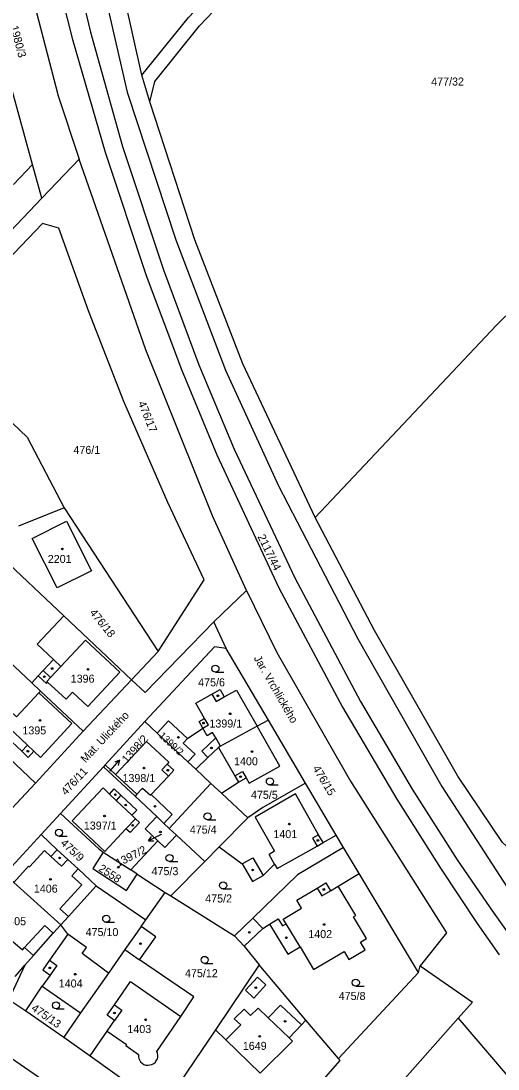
# Model space of a CAD drawing. Extents: x -679220 to -673243, y -1075091 to -1066557.
# Drawn here: x -675699.3 to -675598.1, y -1072325.9 to -1072103.3 of the extents above; entities that cross this region are included whole.
import ezdxf

# ---------------------------------------------------------------- set-up
doc = ezdxf.new("R2010")
doc.units = 0
for name, color, linetype in [('Hranice parcel', 7, 'Continuous'), ('Parcelní čísla', 7, 'Continuous'), ('Pop  PČ popisy', 7, 'Continuous'), ('Poz předměty', 7, 'Continuous'), ('Vnitřní kresba', 7, 'Continuous'), ('Značky budov', 7, 'Continuous'), ('Značky kultur', 7, 'Continuous')]:
    doc.layers.add(name, color=color, linetype=linetype)

msp = doc.modelspace()

# ---------------------------------------------------------------- linework, layer by layer
at = {"layer": 'Hranice parcel'}
for p, q in [((-675673.66, -1072114.8), (-675686.88, -1072055.23)), ((-675671.95, -1072120.45), (-675673.66, -1072114.8)), ((-675696.86, -1072133.78), (-675701.37, -1072117.47)), ((-675700.9, -1072138.01), (-675696.86, -1072133.78)), ((-675694.91, -1072140.93), (-675696.86, -1072133.78)), ((-675687, -1072132.64), (-675694.91, -1072140.93)), ((-675690.19, -1072206.73), (-675699.85, -1072210.59)), ((-675690.19, -1072206.73), (-675670.21, -1072237.22)), ((-675704.87, -1072215.84), (-675690.25, -1072229.64)), ((-675658.41, -1072230.92), (-675651.43, -1072224.24)), ((-675697.03, -1072243.89), (-675715.28, -1072226.72)), ((-675690.25, -1072229.64), (-675675.87, -1072243.22)), ((-675655.8, -1072236.62), (-675658.41, -1072230.92)), ((-675646.8, -1072251.8), (-675655.8, -1072236.62)), ((-675670.21, -1072237.22), (-675675.87, -1072243.22)), ((-675686.1, -1072254.17), (-675675.87, -1072243.22)), ((-675697.03, -1072243.89), (-675695.17, -1072245.64)), ((-675686.1, -1072254.17), (-675695.17, -1072245.64)), ((-675673.03, -1072252.09), (-675681.45, -1072261.29)), ((-675670.41, -1072254.55), (-675673.03, -1072252.09)), ((-675646.8, -1072251.8), (-675649.22, -1072253.12)), ((-675638.91, -1072265.18), (-675646.8, -1072251.8)), ((-675696.22, -1072265.18), (-675686.1, -1072254.17)), ((-675663.89, -1072260.67), (-675670.41, -1072254.55)), ((-675681.45, -1072261.29), (-675681.83, -1072261.71)), ((-675662.19, -1072262.26), (-675663.89, -1072260.67)), ((-675681.83, -1072261.71), (-675690.93, -1072271.66)), ((-675675.12, -1072267.99), (-675681.83, -1072261.71)), ((-675659.01, -1072265.24), (-675662.19, -1072262.26)), ((-675705.9, -1072275.51), (-675696.22, -1072265.18)), ((-675667.86, -1072274.8), (-675659.01, -1072265.24)), ((-675659.01, -1072265.24), (-675656.74, -1072267.36)), ((-675632.4, -1072276.24), (-675638.91, -1072265.18)), ((-675670.52, -1072272.31), (-675675.12, -1072267.99)), ((-675651.17, -1072272.59), (-675656.74, -1072267.36)), ((-675690.93, -1072271.66), (-675695.05, -1072276.14)), ((-675651.17, -1072272.59), (-675657.25, -1072278.74)), ((-675695.05, -1072276.14), (-675702.81, -1072284.58)), ((-675666.31, -1072276.26), (-675667.86, -1072274.8)), ((-675660.33, -1072281.85), (-675666.31, -1072276.26)), ((-675630.88, -1072278.84), (-675632.4, -1072276.24)), ((-675675.99, -1072283.61), (-675670.3, -1072277.43)), ((-675657.25, -1072278.74), (-675660.33, -1072281.85)), ((-675627.53, -1072284.42), (-675630.88, -1072278.84)), ((-675681.87, -1072279.86), (-675675.99, -1072283.61)), ((-675674.69, -1072284.54), (-675675.99, -1072283.61)), ((-675660.33, -1072281.85), (-675667.54, -1072289.14)), ((-675674.69, -1072284.54), (-675668.69, -1072288.42)), ((-675614.96, -1072305.4), (-675627.53, -1072284.42)), ((-675683.37, -1072287.03), (-675672.8, -1072294.25)), ((-675672.8, -1072294.25), (-675668.69, -1072288.42)), ((-675668.69, -1072288.42), (-675667.54, -1072289.14)), ((-675667.54, -1072289.14), (-675654.03, -1072297.62)), ((-675673.81, -1072295.67), (-675672.8, -1072294.25)), ((-675654.03, -1072297.62), (-675651.92, -1072299.85)), ((-675651.92, -1072299.85), (-675648.74, -1072303.81)), ((-675698.51, -1072303.87), (-675696.67, -1072301.8)), ((-675698.51, -1072303.87), (-675701.9, -1072311.14)), ((-675700.58, -1072306.26), (-675698.51, -1072303.87)), ((-675680.72, -1072305.54), (-675686.66, -1072313.99)), ((-675648.74, -1072303.81), (-675658.05, -1072317.58)), ((-675638.83, -1072315.52), (-675648.74, -1072303.81)), ((-675631.9, -1072323.72), (-675614.96, -1072305.4)), ((-675614.96, -1072305.4), (-675614.58, -1072304.01)), ((-675701.9, -1072311.14), (-675698.3, -1072313.6)), ((-675698.3, -1072313.6), (-675690.25, -1072319.15)), ((-675686.66, -1072313.99), (-675690.25, -1072319.15)), ((-675631.9, -1072323.72), (-675638.83, -1072315.52)), ((-675635.81, -1072348.19), (-675606.52, -1072315.16)), ((-675690.25, -1072319.15), (-675684.63, -1072323.15)), ((-675658.05, -1072317.58), (-675669.24, -1072334.12)), ((-675684.63, -1072323.15), (-675669.24, -1072334.12))]:
    msp.add_line(p, q, dxfattribs=at)
for points in [[(-675734.17, -1071838.14), (-675727.92, -1071869.06), (-675703.55, -1071993.04), (-675690.45, -1072058.85), (-675676.8, -1072118.37), (-675666.48, -1072149.75), (-675655.92, -1072177.48), (-675644.67, -1072202.06), (-675627.82, -1072234.57), (-675609.97, -1072265.91), (-675595.28, -1072288.62)], [(-675673.66, -1072114.8), (-675663.74, -1072102.5), (-675644.16, -1072081.76), (-675598.34, -1072038.2)], [(-675671.95, -1072120.45), (-675670.91, -1072116.13), (-675661.41, -1072104.3), (-675642.11, -1072083.95), (-675596.14, -1072040.03)], [(-675702.81, -1072072.97), (-675698.86, -1072090.46), (-675691.46, -1072119.14), (-675687, -1072132.64)], [(-675527.13, -1072097.75), (-675598.36, -1072167.91), (-675636.9, -1072208.76)], [(-675636.9, -1072208.76), (-675652.22, -1072176.08), (-675662.43, -1072149.75), (-675671.95, -1072120.45)], [(-675651.43, -1072224.24), (-675658.67, -1072208.41), (-675672.85, -1072173.15), (-675687, -1072132.64)], [(-675694.91, -1072140.93), (-675721.81, -1072169.15), (-675719.13, -1072171.69)], [(-675670.21, -1072237.22), (-675660.45, -1072222.03), (-675668.15, -1072205.56), (-675677.49, -1072184.08), (-675684.97, -1072164.88), (-675691.29, -1072147.32), (-675694.77, -1072146.33), (-675719.13, -1072171.69)], [(-675705.88, -1072184.22), (-675697.99, -1072191.67), (-675690.19, -1072206.73)], [(-675689.66, -1072209.53), (-675684.35, -1072220.08), (-675691.63, -1072223.67), (-675696.93, -1072213.21), (-675689.66, -1072209.53)], [(-675588.59, -1072283.25), (-675590.86, -1072283.57), (-675597.09, -1072277.84), (-675606.59, -1072263.7), (-675624.31, -1072232.74), (-675636.9, -1072208.76)], [(-675651.43, -1072224.24), (-675645.02, -1072237.47), (-675629.39, -1072264.76), (-675609.01, -1072296.97), (-675614.58, -1072304.01)], [(-675690.25, -1072229.64), (-675695.91, -1072235.64), (-675692.45, -1072238.94), (-675694.63, -1072241.26), (-675695.69, -1072242.4), (-675697.03, -1072243.89)], [(-675675.87, -1072243.22), (-675673, -1072245.92), (-675658.41, -1072230.92)], [(-675655.8, -1072236.62), (-675658.25, -1072236.27), (-675673.03, -1072252.09)], [(-675675.24, -1072344.8), (-675677.06, -1072343.56), (-675675.65, -1072341.45), (-675809.62, -1072248.86), (-675810.47, -1072252.39), (-675814.41, -1072249.48), (-675828.02, -1072240.66), (-675831.19, -1072238.38)], [(-675695.17, -1072245.64), (-675695.53, -1072246.03), (-675700.26, -1072251.11), (-675700.48, -1072250.91), (-675706.57, -1072245.42), (-675711.73, -1072250.64)], [(-675663.99, -1072255.71), (-675660.73, -1072253.52), (-675661.52, -1072252.12), (-675660.34, -1072251.45), (-675662.19, -1072248.19), (-675658.8, -1072246.3), (-675657.06, -1072245.32), (-675656.18, -1072246.88), (-675653.59, -1072245.44), (-675649.22, -1072253.12)], [(-675696.22, -1072265.18), (-675701.93, -1072259.82), (-675706.03, -1072255.98), (-675707.09, -1072254.99), (-675710.05, -1072252.21), (-675710.16, -1072252.11), (-675711.46, -1072250.88), (-675711.73, -1072250.64)], [(-675670.41, -1072254.55), (-675667.99, -1072251.98), (-675663.99, -1072255.71)], [(-675649.22, -1072253.12), (-675656.97, -1072257.36), (-675657.4, -1072257.61), (-675659.64, -1072259.78), (-675662.19, -1072262.26)], [(-675656.74, -1072267.36), (-675653.19, -1072265), (-675651.53, -1072264.06), (-675650.86, -1072265.23), (-675644.41, -1072261.56), (-675649.22, -1072253.12)], [(-675663.99, -1072255.71), (-675664.89, -1072256.67), (-675662.35, -1072259.03), (-675663.89, -1072260.67)], [(-675681.45, -1072261.29), (-675679.24, -1072263.39), (-675674.73, -1072267.57), (-675675.12, -1072267.99)], [(-675638.91, -1072265.18), (-675647.97, -1072270.34), (-675651.17, -1072272.59)], [(-675690.93, -1072271.66), (-675682.82, -1072279.13), (-675681.87, -1072279.86)], [(-675670.3, -1072277.43), (-675672.96, -1072274.92), (-675670.52, -1072272.31)], [(-675667.86, -1072274.8), (-675668.97, -1072273.76), (-675670.52, -1072272.31)], [(-675683.37, -1072287.03), (-675687.2, -1072283.39), (-675689.4, -1072281.4), (-675691.65, -1072279.37), (-675695.05, -1072276.14)], [(-675670.3, -1072277.43), (-675668.76, -1072278.89), (-675666.31, -1072276.26)], [(-675657.25, -1072278.74), (-675652.36, -1072282.36), (-675650.18, -1072286.06), (-675647.91, -1072284.83), (-675645.5, -1072282.4), (-675644.96, -1072283.36), (-675636.49, -1072278.56), (-675635.21, -1072277.83), (-675632.4, -1072276.24)], [(-675630.88, -1072278.84), (-675640.61, -1072284.65), (-675650.13, -1072293.87), (-675654.03, -1072297.62)], [(-675681.87, -1072279.86), (-675684.11, -1072283.3), (-675676.94, -1072288.01), (-675674.69, -1072284.54)], [(-675690.86, -1072295.31), (-675700.88, -1072286.3), (-675702.81, -1072284.58)], [(-675651.92, -1072299.85), (-675648, -1072296.07), (-675646.55, -1072295.16), (-675642.71, -1072301.51), (-675640.09, -1072299.95), (-675637.2, -1072304.82), (-675630.71, -1072300.99), (-675629.71, -1072302.68), (-675626.28, -1072300.62), (-675627.27, -1072298.95), (-675625.97, -1072298.18), (-675628.73, -1072293.57), (-675628.28, -1072293.3), (-675631.98, -1072287.09), (-675627.53, -1072284.42)], [(-675690.86, -1072295.31), (-675689.27, -1072293.55), (-675683.37, -1072287.03)], [(-675696.67, -1072301.8), (-675692.48, -1072297.08), (-675690.86, -1072295.31)], [(-675680.72, -1072305.54), (-675686.36, -1072301.42), (-675685.4, -1072300.1), (-675689.41, -1072297.31), (-675690.86, -1072295.31)], [(-675673.81, -1072295.67), (-675677.27, -1072300.54), (-675680.72, -1072305.54)], [(-675670.5, -1072322.19), (-675665.37, -1072314.74), (-675662.61, -1072310.58), (-675674.15, -1072302.73), (-675670.71, -1072297.84), (-675673.81, -1072295.67)], [(-675704.61, -1072298.25), (-675702.38, -1072300.29), (-675701.04, -1072298.81), (-675699.04, -1072300.63), (-675698.59, -1072300.14), (-675696.67, -1072301.8)], [(-675614.58, -1072304.01), (-675603.5, -1072311.74), (-675606.52, -1072315.16)], [(-675698.3, -1072313.6), (-675694.83, -1072308.31), (-675686.66, -1072313.99)], [(-675658.05, -1072317.58), (-675655.81, -1072319.75), (-675648.53, -1072326.82), (-675641.67, -1072320.01), (-675642.38, -1072319.3), (-675639.79, -1072316.55), (-675638.83, -1072315.52)], [(-675606.52, -1072315.16), (-675589.88, -1072334.57), (-675584.91, -1072331.48), (-675555.87, -1072366.37)], [(-675684.63, -1072323.15), (-675681.02, -1072317.88), (-675676.92, -1072320.74), (-675677.08, -1072320.97), (-675674.38, -1072322.85)], [(-675674.38, -1072322.85), (-675674.4, -1072323.3), (-675674.31, -1072323.73), (-675674.13, -1072324.14), (-675673.96, -1072324.39), (-675673.64, -1072324.7), (-675673.27, -1072324.94), (-675672.84, -1072325.08), (-675672.4, -1072325.12), (-675671.96, -1072325.07), (-675671.53, -1072324.95), (-675671.14, -1072324.75), (-675670.8, -1072324.46), (-675670.67, -1072324.3), (-675670.44, -1072323.91), (-675670.31, -1072323.49), (-675670.28, -1072323.05), (-675670.34, -1072322.6), (-675670.5, -1072322.19)], [(-675669.24, -1072334.12), (-675655.8, -1072343.03), (-675653.77, -1072343.98), (-675652.23, -1072344.22), (-675650.78, -1072343.84), (-675649.38, -1072343.04), (-675648.22, -1072342.16), (-675645.05, -1072339.48), (-675631.58, -1072324.1), (-675631.9, -1072323.72)]]:
    msp.add_lwpolyline(points, dxfattribs=at)
at = {"layer": 'Pop  PČ popisy'}
for p, q in [((-675680.4, -1072262.58), (-675678.39, -1072260.35)), ((-675678.39, -1072260.35), (-675679.43, -1072260.76)), ((-675678.39, -1072260.35), (-675678.69, -1072261.43)), ((-675680.48, -1072262.67), (-675680.4, -1072262.58)), ((-675669.57, -1072276.1), (-675672.27, -1072277.42)), ((-675672.27, -1072277.42), (-675671.59, -1072276.53)), ((-675669.47, -1072276.05), (-675669.57, -1072276.1)), ((-675672.27, -1072277.42), (-675671.15, -1072277.43))]:
    msp.add_line(p, q, dxfattribs=at)
at = {"layer": 'Poz předměty'}
for p, q in [((-675695.49, -1072079.08), (-675688.4, -1072107.18)), ((-675691.13, -1072078.96), (-675684.55, -1072105.63)), ((-675688.4, -1072107.18), (-675681.46, -1072131.16)), ((-675684.55, -1072105.63), (-675677.76, -1072129.93)), ((-675677.76, -1072129.93), (-675669.1, -1072156.12)), ((-675681.46, -1072131.16), (-675672.79, -1072157.31)), ((-675669.1, -1072156.12), (-675661.58, -1072176.34)), ((-675672.79, -1072157.31), (-675665.26, -1072177.3)), ((-675661.58, -1072176.34), (-675654.09, -1072194.25)), ((-675665.26, -1072177.3), (-675657.72, -1072195.43)), ((-675654.09, -1072194.25), (-675641.17, -1072221.57)), ((-675657.72, -1072195.43), (-675644.6, -1072223.69)), ((-675641.17, -1072221.57), (-675627.24, -1072247.86)), ((-675644.6, -1072223.69), (-675631.08, -1072249.06)), ((-675627.24, -1072247.86), (-675616.29, -1072266.51)), ((-675631.08, -1072249.06), (-675619.51, -1072268.61)), ((-675616.29, -1072266.51), (-675606.74, -1072281.52)), ((-675619.51, -1072268.61), (-675610.28, -1072283.29)), ((-675610.28, -1072283.29), (-675602.52, -1072295)), ((-675606.74, -1072281.52), (-675599.13, -1072292.63)), ((-675599.13, -1072292.63), (-675594.24, -1072299.49)), ((-675602.52, -1072295), (-675597.79, -1072301.64))]:
    msp.add_line(p, q, dxfattribs=at)
at = {"layer": 'Vnitřní kresba'}
for p, q in [((-675685.63, -1072234.8), (-675690.87, -1072240.43)), ((-675678.32, -1072241.61), (-675685.63, -1072234.8)), ((-675690.87, -1072240.43), (-675692.45, -1072238.94)), ((-675693.07, -1072242.72), (-675694.63, -1072241.26)), ((-675690.87, -1072240.43), (-675693.07, -1072242.72)), ((-675695.69, -1072242.4), (-675693.94, -1072244.04)), ((-675693.86, -1072243.57), (-675693.07, -1072242.72)), ((-675693.67, -1072243.74), (-675693.86, -1072243.57)), ((-675685.13, -1072248.92), (-675678.32, -1072241.61)), ((-675693.94, -1072244.04), (-675693.67, -1072243.74)), ((-675693.67, -1072243.74), (-675689.73, -1072247.37)), ((-675695.53, -1072246.03), (-675688.5, -1072252.55)), ((-675689.73, -1072247.37), (-675688.36, -1072245.9)), ((-675688.36, -1072245.9), (-675685.13, -1072248.92)), ((-675658.8, -1072246.3), (-675657.93, -1072247.85)), ((-675657.93, -1072247.85), (-675656.18, -1072246.88)), ((-675659.55, -1072252.84), (-675660.34, -1072251.45)), ((-675703.39, -1072254.47), (-675699.18, -1072258.43)), ((-675702.14, -1072253.13), (-675697.94, -1072257.12)), ((-675695.21, -1072259.72), (-675688.5, -1072252.55)), ((-675660.73, -1072253.52), (-675659.55, -1072252.84)), ((-675659.82, -1072255.11), (-675660.73, -1072253.52)), ((-675658.64, -1072254.43), (-675659.82, -1072255.11)), ((-675658, -1072255.56), (-675658.64, -1072254.43)), ((-675679.24, -1072263.39), (-675672.68, -1072256.33)), ((-675672.68, -1072256.33), (-675667.93, -1072260.76)), ((-675660.95, -1072258.43), (-675658, -1072255.56)), ((-675656.97, -1072257.36), (-675658, -1072255.56)), ((-675699.18, -1072258.43), (-675697.94, -1072257.12)), ((-675699.18, -1072258.43), (-675697.81, -1072259.72)), ((-675697.94, -1072257.12), (-675696.58, -1072258.42)), ((-675697.81, -1072259.72), (-675696.58, -1072258.42)), ((-675696.58, -1072258.42), (-675695.21, -1072259.72)), ((-675659.64, -1072259.78), (-675660.95, -1072258.43)), ((-675657.4, -1072257.61), (-675653.95, -1072263.66)), ((-675668.27, -1072261.13), (-675669.43, -1072262.38)), ((-675667.93, -1072260.76), (-675668.27, -1072261.13)), ((-675668.27, -1072261.13), (-675666.88, -1072262.42)), ((-675669.43, -1072262.38), (-675668.03, -1072263.69)), ((-675666.88, -1072262.42), (-675668.03, -1072263.69)), ((-675653.95, -1072263.66), (-675652.29, -1072262.72)), ((-675652.29, -1072262.72), (-675651.53, -1072264.06)), ((-675668.03, -1072263.69), (-675671.68, -1072267.59)), ((-675653.95, -1072263.66), (-675653.19, -1072265)), ((-675688.47, -1072273.23), (-675681.91, -1072266.21)), ((-675680.55, -1072267.51), (-675681.91, -1072266.21)), ((-675680.55, -1072267.51), (-675679.53, -1072266.43)), ((-675679.14, -1072268.85), (-675680.55, -1072267.51)), ((-675679.53, -1072266.43), (-675678.12, -1072267.78)), ((-675678.12, -1072267.78), (-675679.14, -1072268.85)), ((-675678.12, -1072267.78), (-675674.76, -1072270.93)), ((-675674.73, -1072267.57), (-675673.5, -1072266.26)), ((-675673.5, -1072266.26), (-675671.86, -1072267.78)), ((-675671.86, -1072267.78), (-675671.68, -1072267.59)), ((-675671.68, -1072267.59), (-675667.22, -1072271.89)), ((-675641.05, -1072267.5), (-675649.62, -1072272.4)), ((-675636.16, -1072276.15), (-675641.05, -1072267.5)), ((-675675.79, -1072272.03), (-675679.14, -1072268.85)), ((-675674.76, -1072270.93), (-675675.79, -1072272.03)), ((-675675.03, -1072272.75), (-675675.79, -1072272.03)), ((-675668.97, -1072273.76), (-675667.22, -1072271.89)), ((-675649.62, -1072272.4), (-675645.48, -1072279.67)), ((-675688.47, -1072273.23), (-675681.52, -1072279.75)), ((-675677.09, -1072274.92), (-675675.03, -1072272.75)), ((-675674.16, -1072273.57), (-675676.18, -1072275.69)), ((-675675.03, -1072272.75), (-675674.16, -1072273.57)), ((-675681.52, -1072279.75), (-675677.09, -1072274.92)), ((-675676.18, -1072275.69), (-675677.09, -1072274.92)), ((-675636.16, -1072276.15), (-675637.45, -1072276.88)), ((-675637.45, -1072276.88), (-675636.49, -1072278.56)), ((-675635.21, -1072277.83), (-675636.16, -1072276.15)), ((-675697.54, -1072282.98), (-675694.37, -1072279.51)), ((-675694.37, -1072279.51), (-675692.97, -1072280.8)), ((-675692.97, -1072280.8), (-675691.65, -1072279.37)), ((-675692.97, -1072280.8), (-675690.74, -1072282.85)), ((-675690.74, -1072282.85), (-675689.4, -1072281.4)), ((-675652.36, -1072282.36), (-675650.11, -1072281.09)), ((-675650.11, -1072281.09), (-675647.91, -1072284.83)), ((-675645.48, -1072279.67), (-675646.67, -1072280.34)), ((-675645.5, -1072282.4), (-675646.67, -1072280.34)), ((-675700.88, -1072286.3), (-675697.71, -1072282.83)), ((-675697.71, -1072282.83), (-675697.54, -1072282.98)), ((-675687.2, -1072283.39), (-675688.55, -1072284.86)), ((-675688.55, -1072284.86), (-675686.44, -1072286.8)), ((-675686.44, -1072286.8), (-675691.07, -1072291.91)), ((-675640.8, -1072290.05), (-675636.45, -1072287.48)), ((-675636.45, -1072287.48), (-675634.61, -1072286.38)), ((-675636.45, -1072287.48), (-675635.46, -1072289.15)), ((-675635.46, -1072289.15), (-675633.62, -1072288.06)), ((-675634.61, -1072286.38), (-675633.62, -1072288.06)), ((-675633.62, -1072288.06), (-675631.98, -1072287.09)), ((-675639.77, -1072291.78), (-675640.8, -1072290.05)), ((-675691.07, -1072291.91), (-675689.27, -1072293.55)), ((-675643.67, -1072294.09), (-675639.77, -1072291.78)), ((-675650.13, -1072293.87), (-675648, -1072296.07)), ((-675646.55, -1072295.16), (-675644.71, -1072294.03)), ((-675644.71, -1072294.03), (-675643.79, -1072295.52)), ((-675643.07, -1072295.08), (-675643.67, -1072294.09)), ((-675694.3, -1072295.43), (-675698.59, -1072300.14)), ((-675694.3, -1072295.43), (-675692.48, -1072297.08)), ((-675643.79, -1072295.52), (-675643.07, -1072295.08)), ((-675640.09, -1072299.95), (-675643.07, -1072295.08)), ((-675689.41, -1072297.31), (-675693.28, -1072302.82)), ((-675677.27, -1072300.54), (-675674.15, -1072302.73)), ((-675693.28, -1072302.82), (-675694.72, -1072304.88)), ((-675693.28, -1072302.82), (-675691.72, -1072303.91)), ((-675694.72, -1072304.88), (-675693.16, -1072305.98)), ((-675691.72, -1072303.91), (-675693.16, -1072305.98)), ((-675693.16, -1072305.98), (-675694.83, -1072308.31)), ((-675679.49, -1072312.28), (-675676.07, -1072307.37)), ((-675676.07, -1072307.37), (-675665.37, -1072314.74)), ((-675651.67, -1072309.21), (-675649.13, -1072306.42)), ((-675647.33, -1072308.05), (-675649.87, -1072310.85)), ((-675649.13, -1072306.42), (-675647.33, -1072308.05)), ((-675649.87, -1072310.85), (-675651.67, -1072309.21)), ((-675681.05, -1072314.51), (-675679.49, -1072312.28)), ((-675679.49, -1072312.28), (-675677.9, -1072313.4)), ((-675646.85, -1072315.08), (-675644.21, -1072312.35)), ((-675644.21, -1072312.35), (-675639.79, -1072316.55)), ((-675679.45, -1072315.62), (-675681.05, -1072314.51)), ((-675677.9, -1072313.4), (-675679.45, -1072315.62)), ((-675654.06, -1072315.28), (-675651.98, -1072313.21)), ((-675651.98, -1072313.21), (-675650.62, -1072314.58)), ((-675650.62, -1072314.58), (-675649.01, -1072312.98)), ((-675649.01, -1072312.98), (-675646.85, -1072315.08)), ((-675681.02, -1072317.88), (-675679.45, -1072315.62)), ((-675655.81, -1072319.75), (-675652.67, -1072316.52)), ((-675652.67, -1072316.52), (-675654.06, -1072315.28)), ((-675646.85, -1072315.08), (-675642.38, -1072319.3))]:
    msp.add_line(p, q, dxfattribs=at)
at = {"layer": 'Značky budov'}
for centre in [(-675690.55, -1072215.45), (-675692.72, -1072240.85), (-675685.1, -1072241.02), (-675694.39, -1072242.58), (-675657.54, -1072246.63), (-675654.93, -1072250.46), (-675695.31, -1072251.88), (-675660.58, -1072252.44), (-675665.92, -1072255.48), (-675697.86, -1072258.42), (-675658.9, -1072257.73), (-675650.3, -1072258.48), (-675673.21, -1072262.01), (-675668.17, -1072262.45), (-675652.72, -1072263.81), (-675679.3, -1072267.65), (-675677.09, -1072269.85), (-675670.87, -1072270.11), (-675681.59, -1072272.19), (-675675.63, -1072274.17), (-675642.35, -1072273.9), (-675669.72, -1072275.58), (-675636.3, -1072277.38), (-675691.13, -1072281.09), (-675678.68, -1072283.05), (-675650.16, -1072283.64), (-675693.07, -1072285.63), (-675635.04, -1072287.79), (-675650.87, -1072296.91), (-675634.98, -1072295.23), (-675673.96, -1072299.29), (-675643.01, -1072298.05), (-675693.22, -1072304.45), (-675687.81, -1072305.79), (-675649.48, -1072308.66), (-675679.49, -1072314.02), (-675672.86, -1072315.48), (-675643.26, -1072315.79), (-675648.65, -1072318.98)]:
    msp.add_circle(centre, 0.175, dxfattribs=at)
at = {"layer": 'Značky kultur'}
for p, q in [((-675658.05, -1072241.62), (-675656.3, -1072241.62)), ((-675646.49, -1072265.59), (-675644.74, -1072265.59)), ((-675659.73, -1072273.01), (-675657.98, -1072273.01)), ((-675691.26, -1072276.46), (-675689.51, -1072276.46)), ((-675667.8, -1072281.84), (-675666.05, -1072281.84)), ((-675656.41, -1072287.68), (-675654.66, -1072287.68)), ((-675681.23, -1072294.76), (-675679.48, -1072294.76)), ((-675660.35, -1072303.5), (-675658.6, -1072303.5)), ((-675628.25, -1072308.33), (-675626.5, -1072308.33)), ((-675691.88, -1072313.15), (-675690.13, -1072313.15))]:
    msp.add_line(p, q, dxfattribs=at)
for centre in [(-675658.05, -1072240.87), (-675646.49, -1072264.84), (-675659.73, -1072272.26), (-675691.26, -1072275.71), (-675667.8, -1072281.09), (-675656.41, -1072286.93), (-675681.23, -1072294.01), (-675660.35, -1072302.75), (-675628.25, -1072307.58), (-675691.88, -1072312.4)]:
    msp.add_circle(centre, 0.75, dxfattribs=at)

# ---------------------------------------------------------------- texts
at = {"layer": 'Parcelní čísla'}
for s, height, rotation, p in [('1980/3', 1.7, 285, (-675701.61, -1072104.48)), ('476/17', 1.7, 292, (-675674.52, -1072184.43)), ('2117/44', 1.7, 296, (-675649.14, -1072212.83)), ('476/18', 1.7, 309, (-675684.86, -1072229.03)), ('1399/2', 1.5, 317, (-675670.16, -1072255.26)), ('1398/2', 1.7, 48, (-675676.85, -1072261.06)), ('476/11', 1.7, 47, (-675689.77, -1072267.91)), ('476/15', 1.7, 301, (-675637.48, -1072262.07)), ('475/9', 1.7, 317, (-675691.07, -1072278.12)), ('1397/2', 1.7, 27, (-675678.7, -1072283.05)), ('2558', 1.7, 327, (-675683.02, -1072283.73)), ('475/13', 1.7, 325, (-675697.28, -1072313.35))]:
    msp.add_text(s, height=height, rotation=rotation, dxfattribs=at).set_placement(p)
for s, p in [('477/32', (-675612.25, -1072116.98)), ('476/1', (-675688.2, -1072195.24)), ('2201', (-675693.64, -1072218.42)), ('1396', (-675688.78, -1072243.85)), ('475/6', (-675661.72, -1072244.63)), ('1399/1', (-675659.33, -1072253.38)), ('1395', (-675699.03, -1072254.84)), ('1400', (-675654.1, -1072261.4)), ('1398/1', (-675677.78, -1072264.97)), ('475/5', (-675650.51, -1072268.52)), ('1397/1', (-675685.99, -1072275.06)), ('475/4', (-675663.49, -1072275.92)), ('1401', (-675645.75, -1072276.87)), ('475/3', (-675671.61, -1072284.74)), ('1406', (-675696.6, -1072288.46)), ('475/2', (-675660.22, -1072290.55)), ('1405', (-675703.31, -1072295.38)), ('475/10', (-675685.61, -1072297.69)), ('1402', (-675638.34, -1072298.11)), ('475/12', (-675664.51, -1072306.42)), ('1404', (-675691.31, -1072308.6)), ('475/8', (-675631.88, -1072311.26)), ('1403', (-675676.74, -1072318.29)), ('1649', (-675652.24, -1072321.86))]:
    msp.add_text(s, height=1.7, dxfattribs=at).set_placement(p)
at = {"layer": 'Pop  PČ popisy'}
for s, rotation, p in [('Jar. Vrchlického', 300, (-675649.98, -1072238.65)), ('Mat. Ulického', 47, (-675685.63, -1072260.98))]:
    msp.add_text(s, height=1.7, rotation=rotation, dxfattribs=at).set_placement(p)

doc.saveas('drawing.dxf')
